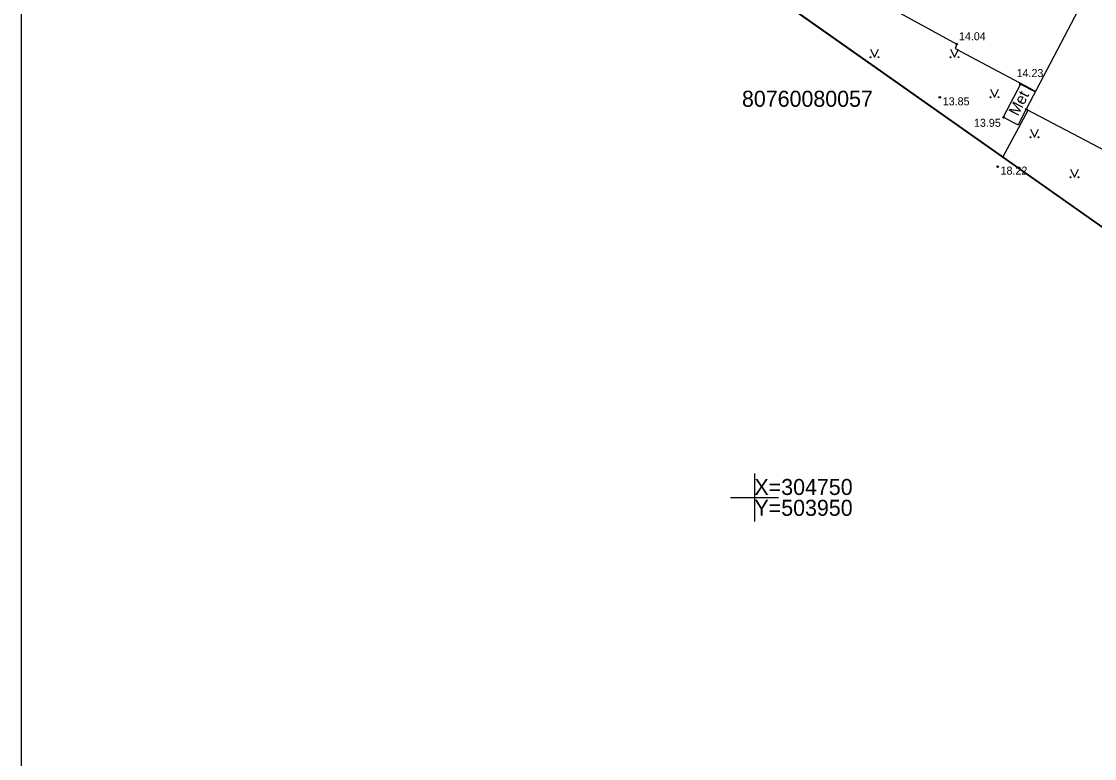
# Model space of a CAD drawing. Extents: x 503904 to 504094, y 304688 to 304960.
# Drawn here: x 503904.2 to 503971.2, y 304733.7 to 304779.7 of the extents above; entities that cross this region are included whole.
import ezdxf

# ---------------------------------------------------------------- set-up
doc = ezdxf.new("R2010")
doc.units = 0
for name, color, linetype in [('BUVE_EKAS_####_####_#', 7, 'Continuous'), ('BUVE_EKAS_BPAL_####_#', 7, 'Continuous'), ('BUVE_EKAS_RAKS_TKST_#', 7, 'Continuous'), ('CELI_CMAL_####_####_#', 7, 'Continuous'), ('GEOD_ELEM_####_####_#', 7, 'Continuous'), ('GEOD_KORD_####_TKST_#', 7, 'Continuous'), ('NORB_ZOGS_ZSTP_####_#', 7, 'Continuous'), ('RAMI_PLAN_####_TKST_#', 7, 'Continuous'), ('RAMI_UZMR_####_####_#', 7, 'Continuous'), ('RELJ_AATZ_####_TKST_#', 7, 'Continuous'), ('RELJ_ELEM_####_####_#', 7, 'Continuous'), ('ROBZ_UZMR_####_####_#', 7, 'Continuous'), ('ROBZ_UZMR_####_TKST_#', 7, 'Continuous'), ('TERT_ELEM_####_####_#', 7, 'Continuous')]:
    doc.layers.add(name, color=color, linetype=linetype)

msp = doc.modelspace()

# ---------------------------------------------------------------- linework, layer by layer
at = {"layer": 'BUVE_EKAS_####_####_#'}
for p, q in [((504000.528, 304838.553), (503966.985, 304774.25)), ((503966.985, 304774.25), (503980.794, 304766.985))]:
    msp.add_line(p, q, dxfattribs=at)
at = {"layer": 'BUVE_EKAS_BPAL_####_#'}
for p, q in [((503966.617, 304775.819), (503965.541, 304773.756)), ((503966.617, 304775.819), (503967.55, 304775.332)), ((503965.541, 304773.756), (503966.473, 304773.269)), ((503966.985, 304774.25), (503966.473, 304773.269))]:
    msp.add_line(p, q, dxfattribs=at)
at = {"layer": 'CELI_CMAL_####_####_#'}
msp.add_lwpolyline([(503959.037, 304792.215), (503958.033, 304789.951), (503956.005, 304791.021), (503952.396, 304783.936), (503962.641, 304778.325), (503962.541, 304778.045), (503967.206, 304775.557), (503967.568, 304775.368)], dxfattribs=at)
at = {"layer": 'GEOD_ELEM_####_####_#'}
for p, q in [((503950, 304751.5), (503950, 304750)), ((503948.5, 304750), (503950, 304750)), ((503950, 304750), (503950, 304748.5)), ((503950, 304750), (503951.5, 304750))]:
    msp.add_line(p, q, dxfattribs=at)
at = {"layer": 'NORB_ZOGS_ZSTP_####_#'}
msp.add_lwpolyline([(503965.515, 304771.264), (503967.1, 304774.19)], dxfattribs=at)
at = {"layer": 'RAMI_PLAN_####_TKST_#'}
msp.add_lwpolyline([(503904.204, 304823.741), (504093.703, 304823.741), (504093.703, 304687.633), (503904.204, 304687.633)], close=True, dxfattribs=at)
at = {"layer": 'RAMI_UZMR_####_####_#'}
msp.add_lwpolyline([(503923.253, 304801.015), (503981.982, 304759.672), (503995.48, 304748.813), (504027.75, 304817.255), (504060.02, 304885.696), (504048.875, 304885.773), (504036.803, 304888.853), (503994.536, 304908.303), (503981.123, 304894.75), (503978.518, 304892.436), (503950.886, 304846.726), (503923.253, 304801.015)], dxfattribs=at)
at = {"layer": 'RELJ_ELEM_####_####_#'}
for centre in [(503962.641, 304778.325), (503966.617, 304775.819), (503961.579, 304774.995), (503965.567, 304773.742), (503966.985, 304774.25), (503965.192, 304770.668)]:
    msp.add_circle(centre, 0.05, dxfattribs=at)
at = {"layer": 'ROBZ_UZMR_####_####_#'}
msp.add_lwpolyline([(503923.29, 304801.044), (503978.518, 304892.436), (503981.123, 304894.75), (504030.463, 304860.121), (503981.982, 304759.672)], close=True, dxfattribs=at)
msp.add_lwpolyline([(503918.172, 304804.652), (503923.29, 304801.044), (503981.982, 304759.672), (503976.441, 304742.944)], dxfattribs=at)
at = {"layer": 'TERT_ELEM_####_####_#'}
for p, q in [((503957.25, 304778), (503957.5, 304777.5)), ((503957.5, 304777.5), (503957.75, 304778)), ((503962.25, 304778), (503962.5, 304777.5)), ((503962.5, 304777.5), (503962.75, 304778)), ((503964.75, 304775.5), (503965, 304775)), ((503965, 304775), (503965.25, 304775.5)), ((503967.25, 304773), (503967.5, 304772.5)), ((503967.5, 304772.5), (503967.75, 304773)), ((503969.75, 304770.5), (503970, 304770)), ((503970, 304770), (503970.25, 304770.5))]:
    msp.add_line(p, q, dxfattribs=at)
for centre, radius in [((503957.25, 304777.5), 0.028), ((503957.75, 304777.5), 0.0263), ((503962.25, 304777.5), 0.028), ((503962.75, 304777.5), 0.0263), ((503964.75, 304775), 0.028), ((503965.25, 304775), 0.0263), ((503967.25, 304772.5), 0.028), ((503967.75, 304772.5), 0.0263), ((503969.75, 304770), 0.028), ((503970.25, 304770), 0.0263)]:
    msp.add_circle(centre, radius, dxfattribs=at)

# ---------------------------------------------------------------- texts
at = {"layer": 'BUVE_EKAS_RAKS_TKST_#'}
msp.add_text('Met', height=0.7, rotation=62.45166, dxfattribs=at).set_placement((503966.463, 304773.781))
at = {"layer": 'GEOD_KORD_####_TKST_#'}
for s, p in [('X=304750', (503950, 304750.15)), ('Y=503950', (503950, 304748.85))]:
    msp.add_text(s, height=1, dxfattribs=at).set_placement(p)
at = {"layer": 'RELJ_AATZ_####_TKST_#'}
for s, p in [(' 14.04', (503962.592, 304778.562)), (' 14.23', (503966.193, 304776.262)), (' 13.85', (503961.579, 304774.495)), (' 13.95', (503963.531, 304773.153)), (' 18.22', (503965.192, 304770.168))]:
    msp.add_text(s, height=0.5, dxfattribs=at).set_placement(p)
at = {"layer": 'ROBZ_UZMR_####_TKST_#'}
msp.add_text('80760080057', height=1, dxfattribs=at).set_placement((503949.219, 304774.406))

doc.saveas('drawing.dxf')
